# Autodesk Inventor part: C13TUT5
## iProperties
Created: 2005-03
Part Number: C13TUT5
Document SubType Name: Modeling
Designer: CADCIM
Manufacturer: Standard
Standards Organization: Custom
Author: CADCIM
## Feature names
1. Split1
2. Split2
3. Split3
4. Split4
5. Split5
6. Fillet1
